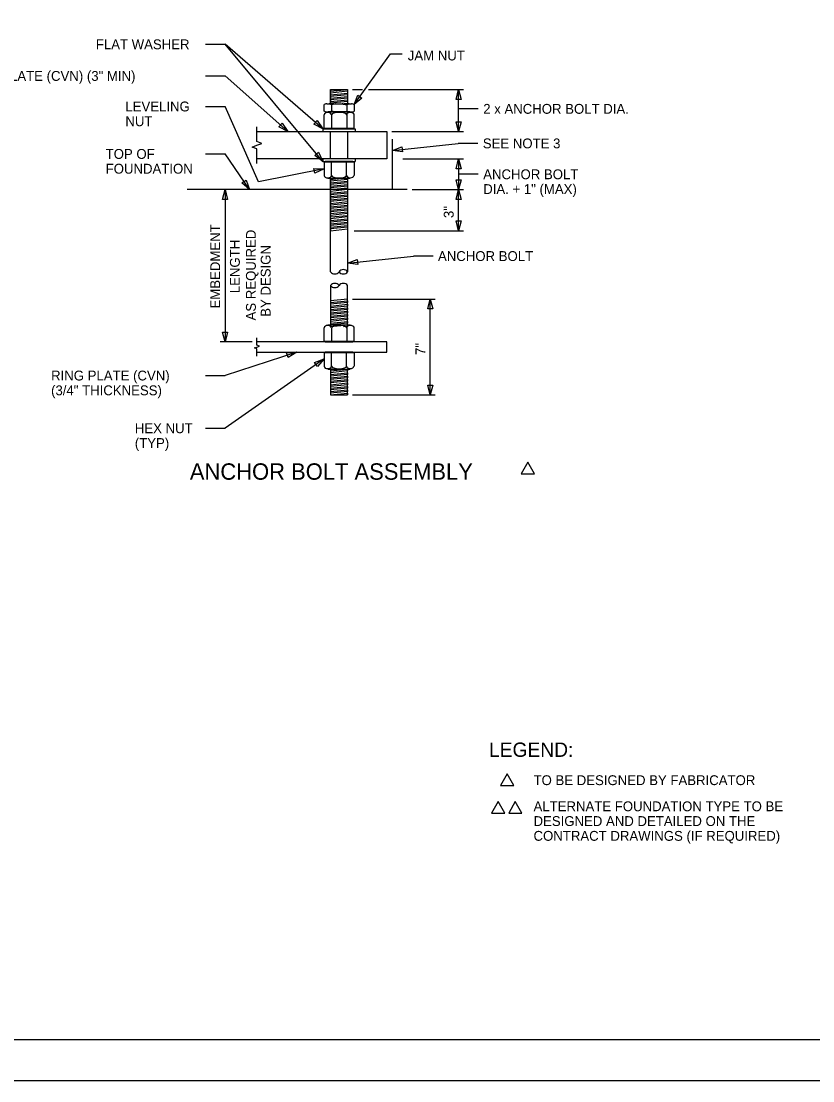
# Model space of a CAD drawing. Extents: x 1299104.6 to 1299141.4, y 239713.3 to 239735.3.
# Drawn here: x 1299118.81 to 1299128.46, y 239713.27 to 239726.18 of the extents above; entities that cross this region are included whole.
import ezdxf

# ---------------------------------------------------------------- set-up
doc = ezdxf.new("R2010")
doc.units = 0
for name, color, linetype in [('DIM TXT', 7, 'Continuous'), ('GS_plotshape_p', 7, 'Continuous'), ('Level 1', 7, 'Continuous'), ('Level 3', 7, 'Continuous'), ('Level 4', 7, 'Continuous'), ('Level 8', 7, 'Continuous')]:
    doc.layers.add(name, color=color, linetype=linetype)

msp = doc.modelspace()

# ---------------------------------------------------------------- linework, layer by layer
at = {"layer": 'DIM TXT'}
for points in [[(1299122.582, 239725.345), (1299122.582, 239725.324), (1299122.79, 239725.345), (1299122.79, 239725.324), (1299122.582, 239725.303), (1299122.582, 239725.282), (1299122.79, 239725.303), (1299122.79, 239725.282), (1299122.582, 239725.261), (1299122.582, 239725.241), (1299122.79, 239725.261), (1299122.79, 239725.241)], [(1299122.582, 239725.261), (1299122.582, 239725.241), (1299122.79, 239725.261), (1299122.79, 239725.241), (1299122.582, 239725.22), (1299122.582, 239725.199), (1299122.79, 239725.22), (1299122.79, 239725.199), (1299122.582, 239725.178), (1299122.582, 239725.178), (1299122.582, 239725.178)]]:
    msp.add_lwpolyline(points, dxfattribs=at)
for points in [[(1299124.905, 239720.667), (1299125.067, 239720.667), (1299124.986, 239720.807)], [(1299124.653, 239716.869), (1299124.815, 239716.869), (1299124.734, 239717.01)], [(1299124.543, 239716.534), (1299124.706, 239716.534), (1299124.625, 239716.675)], [(1299124.752, 239716.534), (1299124.914, 239716.534), (1299124.833, 239716.675)]]:
    msp.add_lwpolyline(points, close=True, dxfattribs=at)
at = {"layer": 'GS_plotshape_p'}
msp.add_lwpolyline([(1299104.622, 239735.273), (1299138.622, 239735.273), (1299138.622, 239713.273), (1299104.622, 239713.273)], close=True, dxfattribs=at)
at = {"layer": 'Level 1'}
msp.add_lwpolyline([(1299138.122, 239713.773), (1299106.122, 239713.773), (1299106.122, 239734.773), (1299138.122, 239734.773)], close=True, dxfattribs=at)
at = {"layer": 'Level 3'}
for p, q in [((1299122.516, 239725.166), (1299122.503, 239725.162)), ((1299122.503, 239725.08), (1299122.503, 239725.162)), ((1299122.535, 239725.17), (1299122.837, 239725.17)), ((1299122.593, 239725.159), (1299122.577, 239725.167)), ((1299122.636, 239725.169), (1299122.593, 239725.159)), ((1299122.593, 239725.159), (1299122.593, 239725.083)), ((1299122.736, 239725.169), (1299122.779, 239725.159)), ((1299122.779, 239725.159), (1299122.795, 239725.167)), ((1299122.779, 239725.159), (1299122.779, 239725.083)), ((1299122.856, 239725.166), (1299122.869, 239725.162)), ((1299122.869, 239725.162), (1299122.869, 239725.08)), ((1299122.516, 239725.075), (1299122.503, 239725.08)), ((1299122.504, 239724.876), (1299122.504, 239725.038)), ((1299122.535, 239725.072), (1299122.837, 239725.072)), ((1299122.819, 239725.072), (1299122.554, 239725.072)), ((1299122.593, 239725.083), (1299122.577, 239725.075)), ((1299122.636, 239725.073), (1299122.593, 239725.083)), ((1299122.594, 239725.036), (1299122.594, 239724.876)), ((1299122.686, 239725.072), (1299122.686, 239725.072)), ((1299122.736, 239725.073), (1299122.779, 239725.083)), ((1299122.779, 239725.083), (1299122.795, 239725.075)), ((1299122.779, 239725.037), (1299122.779, 239724.876)), ((1299122.856, 239725.075), (1299122.869, 239725.08)), ((1299122.869, 239724.876), (1299122.869, 239725.039)), ((1299122.49, 239724.866), (1299122.517, 239724.866)), ((1299122.49, 239724.866), (1299122.49, 239724.835)), ((1299122.504, 239724.876), (1299122.869, 239724.876)), ((1299122.517, 239724.875), (1299122.517, 239724.866)), ((1299122.517, 239724.866), (1299122.855, 239724.866)), ((1299122.855, 239724.875), (1299122.855, 239724.866)), ((1299122.855, 239724.866), (1299122.883, 239724.866)), ((1299122.883, 239724.866), (1299122.883, 239724.835)), ((1299121.686, 239724.834), (1299123.269, 239724.834)), ((1299123.269, 239724.834), (1299123.269, 239724.501)), ((1299123.336, 239724.126), (1299123.336, 239724.742)), ((1299123.269, 239724.501), (1299121.686, 239724.501)), ((1299122.49, 239724.501), (1299122.49, 239724.47)), ((1299122.49, 239724.47), (1299122.517, 239724.47)), ((1299122.503, 239724.46), (1299122.503, 239724.297)), ((1299122.868, 239724.46), (1299122.503, 239724.46)), ((1299122.855, 239724.47), (1299122.517, 239724.47)), ((1299122.517, 239724.461), (1299122.517, 239724.47)), ((1299122.593, 239724.299), (1299122.593, 239724.46)), ((1299122.778, 239724.3), (1299122.778, 239724.46)), ((1299122.855, 239724.461), (1299122.855, 239724.47)), ((1299122.855, 239724.47), (1299122.883, 239724.47)), ((1299122.868, 239724.46), (1299122.868, 239724.298)), ((1299122.883, 239724.501), (1299122.883, 239724.47)), ((1299122.553, 239724.264), (1299122.818, 239724.264)), ((1299123.517, 239724.126), (1299120.836, 239724.126)), ((1299122.504, 239722.281), (1299122.504, 239722.444)), ((1299122.819, 239722.477), (1299122.554, 239722.477)), ((1299122.594, 239722.441), (1299122.594, 239722.281)), ((1299122.686, 239722.477), (1299122.686, 239722.477)), ((1299122.779, 239722.442), (1299122.779, 239722.281)), ((1299122.869, 239722.281), (1299122.869, 239722.445)), ((1299123.269, 239722.272), (1299121.686, 239722.272)), ((1299122.504, 239722.281), (1299122.869, 239722.281)), ((1299122.517, 239722.281), (1299122.517, 239722.272)), ((1299122.517, 239722.272), (1299122.855, 239722.272)), ((1299122.855, 239722.281), (1299122.855, 239722.272)), ((1299123.269, 239722.147), (1299123.269, 239722.272)), ((1299121.686, 239722.147), (1299123.269, 239722.147)), ((1299122.503, 239722.137), (1299122.503, 239721.974)), ((1299122.868, 239722.137), (1299122.503, 239722.137)), ((1299122.855, 239722.147), (1299122.517, 239722.147)), ((1299122.517, 239722.138), (1299122.517, 239722.147)), ((1299122.593, 239721.976), (1299122.593, 239722.137)), ((1299122.778, 239721.977), (1299122.778, 239722.137)), ((1299122.855, 239722.138), (1299122.855, 239722.147)), ((1299122.868, 239722.137), (1299122.868, 239721.975)), ((1299122.553, 239721.941), (1299122.818, 239721.941))]:
    msp.add_line(p, q, dxfattribs=at)
for points in [[(1299122.582, 239725.17), (1299122.582, 239725.345), (1299122.79, 239725.345), (1299122.79, 239725.17)], [(1299122.709, 239725.17), (1299122.79, 239725.178), (1299122.79, 239725.178)], [(1299122.582, 239724.501), (1299122.582, 239724.834), (1299122.79, 239724.834), (1299122.79, 239724.501)], [(1299122.582, 239723.126), (1299122.582, 239724.264), (1299122.79, 239724.264), (1299122.79, 239723.126)], [(1299122.582, 239724.251), (1299122.582, 239724.251), (1299122.582, 239724.251), (1299122.713, 239724.264), (1299122.713, 239724.264)], [(1299122.582, 239722.959), (1299122.582, 239722.454)], [(1299122.79, 239722.454), (1299122.79, 239722.959)], [(1299122.582, 239721.941), (1299122.582, 239721.626), (1299122.79, 239721.626), (1299122.79, 239721.941)]]:
    msp.add_lwpolyline(points, dxfattribs=at)
for centre, radius, start, end in [((1299122.535, 239725.116), 0.0541, 90, 110.556), ((1299122.565, 239725.143), 0.0271, 63.4349, 90), ((1299122.648, 239725.116), 0.0541, 90, 102.5288), ((1299122.724, 239725.116), 0.0541, 77.4712, 90), ((1299122.807, 239725.143), 0.0271, 90, 116.5651), ((1299122.837, 239725.116), 0.0541, 69.444, 90), ((1299122.535, 239725.126), 0.0541, 249.444, 270), ((1299122.554, 239725.067), 0.00494, 90, 180), ((1299122.565, 239725.099), 0.0271, 270, 296.5651), ((1299122.648, 239725.126), 0.0541, 257.4712, 270), ((1299122.724, 239725.126), 0.0541, 270, 282.5288), ((1299122.807, 239725.099), 0.0271, 243.4349, 270), ((1299122.819, 239725.067), 0.00494, 0, 90), ((1299122.837, 239725.126), 0.0541, 270, 290.556), ((1299122.553, 239724.269), 0.00494, 180, 270), ((1299122.798, 239724.298), 0.0213, 180, 270), ((1299122.818, 239724.269), 0.00494, 270, 0), ((1299122.634, 239723.165), 0.0651, 216.8699, 323.1301), ((1299122.738, 239723.087), 0.0651, 36.8699, 143.1301), ((1299122.738, 239723.165), 0.0651, 216.8699, 323.1301), ((1299122.634, 239722.92), 0.0651, 36.8699, 143.1301), ((1299122.634, 239722.998), 0.0651, 216.8699, 323.1301), ((1299122.738, 239722.92), 0.0651, 36.8699, 143.1301), ((1299122.554, 239722.472), 0.00494, 90, 180), ((1299122.819, 239722.472), 0.00494, 0, 90), ((1299122.553, 239721.946), 0.00494, 180, 270), ((1299122.818, 239721.946), 0.00494, 270, 0)]:
    msp.add_arc(centre, radius, start, end, dxfattribs=at)
for centre, major_axis, ratio, start_param, end_param in [((1299122.549, 239725.035), (0.0451, 0.0005), 0.679853, 0, 3.035161), ((1299122.686, 239725.036), (-0.0927, -0.0005), 0.335964, 3.141593, 6.283185), ((1299122.824, 239725.036), (-0.0451, 0.0005), 0.679853, 3.248025, 6.283185), ((1299122.548, 239724.3), (0.0451, -0.0005), 0.679853, 3.248025, 6.283185), ((1299122.686, 239724.3), (0.0927, 0.0005), 0.335964, 3.141593, 6.283185), ((1299122.823, 239724.301), (-0.0451, -0.0005), 0.679853, 0, 3.035161), ((1299122.549, 239722.441), (0.0451, 0.0005), 0.679853, 0, 3.035161), ((1299122.686, 239722.442), (-0.0927, -0.0005), 0.335964, 3.141593, 6.283185), ((1299122.824, 239722.442), (-0.0451, 0.0005), 0.679853, 3.248025, 6.283185), ((1299122.548, 239721.977), (0.0451, -0.0005), 0.679853, 3.248025, 6.283185), ((1299122.686, 239721.977), (0.0927, 0.0005), 0.335964, 3.141593, 6.283185), ((1299122.823, 239721.978), (-0.0451, -0.0005), 0.679853, 0, 3.035161)]:
    msp.add_ellipse(centre, major_axis=major_axis, ratio=ratio, start_param=start_param, end_param=end_param, dxfattribs=at)
at = {"layer": 'Level 4'}
for points in [[(1299122.79, 239724.251), (1299122.582, 239724.23), (1299122.582, 239724.209), (1299122.79, 239724.23), (1299122.79, 239724.209), (1299122.582, 239724.188), (1299122.582, 239724.168), (1299122.79, 239724.188), (1299122.79, 239724.168), (1299122.582, 239724.147), (1299122.582, 239724.126), (1299122.79, 239724.147), (1299122.79, 239724.126), (1299122.582, 239724.105), (1299122.582, 239724.084), (1299122.79, 239724.105), (1299122.79, 239724.084), (1299122.582, 239724.063), (1299122.582, 239724.043), (1299122.79, 239724.063), (1299122.79, 239724.043)], [(1299122.79, 239724.043), (1299122.582, 239724.022), (1299122.582, 239724.001), (1299122.79, 239724.022), (1299122.79, 239724.001), (1299122.582, 239723.98), (1299122.582, 239723.959), (1299122.79, 239723.98), (1299122.79, 239723.959), (1299122.582, 239723.938), (1299122.582, 239723.918), (1299122.79, 239723.938), (1299122.79, 239723.918), (1299122.582, 239723.897), (1299122.582, 239723.876), (1299122.79, 239723.897), (1299122.79, 239723.876), (1299122.582, 239723.855), (1299122.582, 239723.834), (1299122.79, 239723.855), (1299122.79, 239723.834)], [(1299122.79, 239723.834), (1299122.582, 239723.813), (1299122.582, 239723.793), (1299122.79, 239723.813), (1299122.79, 239723.793), (1299122.582, 239723.772), (1299122.582, 239723.751), (1299122.79, 239723.772), (1299122.79, 239723.751), (1299122.582, 239723.73), (1299122.582, 239723.709), (1299122.79, 239723.73), (1299122.79, 239723.709), (1299122.582, 239723.688), (1299122.582, 239723.668), (1299122.79, 239723.688), (1299122.79, 239723.668), (1299122.582, 239723.647), (1299122.582, 239723.626), (1299122.79, 239723.647), (1299122.79, 239723.626)], [(1299122.79, 239722.793), (1299122.582, 239722.772), (1299122.582, 239722.751), (1299122.79, 239722.772), (1299122.79, 239722.751)], [(1299122.79, 239722.751), (1299122.582, 239722.73), (1299122.582, 239722.709), (1299122.79, 239722.73), (1299122.79, 239722.709), (1299122.582, 239722.688), (1299122.582, 239722.668), (1299122.79, 239722.688), (1299122.79, 239722.668), (1299122.582, 239722.647), (1299122.582, 239722.626), (1299122.79, 239722.647), (1299122.79, 239722.626), (1299122.582, 239722.605), (1299122.582, 239722.584), (1299122.79, 239722.605), (1299122.79, 239722.584), (1299122.582, 239722.563), (1299122.582, 239722.543), (1299122.79, 239722.563), (1299122.79, 239722.543)], [(1299122.79, 239722.543), (1299122.582, 239722.522), (1299122.582, 239722.501), (1299122.79, 239722.522), (1299122.79, 239722.501), (1299122.582, 239722.48), (1299122.582, 239722.459), (1299122.79, 239722.48), (1299122.79, 239722.459), (1299122.738, 239722.454)], [(1299122.609, 239721.941), (1299122.609, 239721.941), (1299122.582, 239721.938), (1299122.582, 239721.918), (1299122.79, 239721.938), (1299122.79, 239721.918), (1299122.582, 239721.897), (1299122.582, 239721.876), (1299122.79, 239721.897), (1299122.79, 239721.876), (1299122.582, 239721.855), (1299122.582, 239721.834), (1299122.79, 239721.855), (1299122.79, 239721.834)], [(1299122.79, 239721.834), (1299122.582, 239721.813), (1299122.582, 239721.793), (1299122.79, 239721.813), (1299122.79, 239721.793), (1299122.582, 239721.772), (1299122.582, 239721.751), (1299122.79, 239721.772), (1299122.79, 239721.751), (1299122.582, 239721.73), (1299122.582, 239721.709), (1299122.79, 239721.73), (1299122.79, 239721.709), (1299122.582, 239721.688), (1299122.582, 239721.668), (1299122.79, 239721.688), (1299122.79, 239721.668), (1299122.582, 239721.647), (1299122.582, 239721.626), (1299122.79, 239721.647), (1299122.79, 239721.626)]]:
    msp.add_lwpolyline(points, dxfattribs=at)
at = {"layer": 'Level 8'}
for p, q in [((1299121.057, 239725.896), (1299121.297, 239725.896)), ((1299122.49, 239724.866), (1299121.297, 239725.896)), ((1299122.49, 239724.47), (1299121.297, 239725.896)), ((1299122.869, 239725.162), (1299123.312, 239725.779)), ((1299123.312, 239725.779), (1299123.455, 239725.779)), ((1299121.057, 239725.511), (1299121.297, 239725.511)), ((1299122.063, 239724.834), (1299121.297, 239725.511)), ((1299122.85, 239725.345), (1299122.97, 239725.345)), ((1299123.046, 239725.345), (1299124.202, 239725.345)), ((1299124.142, 239724.834), (1299124.142, 239725.345)), ((1299121.057, 239725.139), (1299121.297, 239725.139)), ((1299121.703, 239724.221), (1299121.297, 239725.139)), ((1299124.382, 239725.11), (1299124.142, 239725.11)), ((1299121.686, 239724.712), (1299121.686, 239724.89)), ((1299123.329, 239724.834), (1299124.202, 239724.834)), ((1299121.626, 239724.645), (1299121.686, 239724.668)), ((1299121.686, 239724.623), (1299121.626, 239724.645)), ((1299121.746, 239724.69), (1299121.686, 239724.712)), ((1299121.686, 239724.668), (1299121.746, 239724.69)), ((1299121.686, 239724.445), (1299121.686, 239724.623)), ((1299123.336, 239724.604), (1299124.137, 239724.689)), ((1299124.377, 239724.689), (1299124.137, 239724.689)), ((1299121.057, 239724.561), (1299121.297, 239724.561)), ((1299121.596, 239724.126), (1299121.297, 239724.561)), ((1299123.463, 239724.501), (1299124.202, 239724.501)), ((1299124.142, 239724.501), (1299124.142, 239724.126)), ((1299122.504, 239724.379), (1299121.703, 239724.221)), ((1299124.382, 239724.313), (1299124.142, 239724.313)), ((1299121.297, 239724.126), (1299121.297, 239722.272)), ((1299123.577, 239724.126), (1299124.202, 239724.126)), ((1299123.577, 239724.126), (1299124.202, 239724.126)), ((1299124.142, 239723.626), (1299124.142, 239724.126)), ((1299122.869, 239723.626), (1299124.202, 239723.626)), ((1299122.79, 239723.232), (1299123.591, 239723.317)), ((1299123.831, 239723.317), (1299123.591, 239723.317)), ((1299122.85, 239722.793), (1299123.857, 239722.793)), ((1299123.797, 239721.626), (1299123.797, 239722.793)), ((1299121.626, 239722.272), (1299121.237, 239722.272)), ((1299121.686, 239722.232), (1299121.686, 239722.32)), ((1299122.17, 239722.147), (1299121.297, 239721.862)), ((1299121.656, 239722.198), (1299121.686, 239722.209)), ((1299121.686, 239722.187), (1299121.656, 239722.198)), ((1299121.716, 239722.22), (1299121.686, 239722.232)), ((1299121.686, 239722.209), (1299121.716, 239722.22)), ((1299121.686, 239722.098), (1299121.686, 239722.187)), ((1299122.504, 239722.066), (1299121.297, 239721.22)), ((1299121.057, 239721.862), (1299121.297, 239721.862)), ((1299122.85, 239721.626), (1299123.857, 239721.626)), ((1299121.057, 239721.22), (1299121.297, 239721.22))]:
    msp.add_line(p, q, dxfattribs=at)
for points in [[(1299122.963, 239725.242), (1299122.869, 239725.162), (1299122.914, 239725.277)], [(1299124.112, 239725.225), (1299124.142, 239725.345), (1299124.172, 239725.225)], [(1299121.993, 239724.936), (1299122.063, 239724.834), (1299121.953, 239724.891)], [(1299122.42, 239724.969), (1299122.49, 239724.866), (1299122.38, 239724.924)], [(1299124.172, 239724.954), (1299124.142, 239724.834), (1299124.112, 239724.954)], [(1299123.458, 239724.587), (1299123.336, 239724.604), (1299123.452, 239724.647)], [(1299122.437, 239724.581), (1299122.49, 239724.47), (1299122.39, 239724.543)], [(1299124.112, 239724.381), (1299124.142, 239724.501), (1299124.172, 239724.381)], [(1299122.38, 239724.385), (1299122.504, 239724.379), (1299122.392, 239724.326)], [(1299121.553, 239724.242), (1299121.596, 239724.126), (1299121.503, 239724.208)], [(1299124.172, 239724.246), (1299124.142, 239724.126), (1299124.112, 239724.246)], [(1299121.267, 239724.006), (1299121.297, 239724.126), (1299121.327, 239724.006)], [(1299124.112, 239724.006), (1299124.142, 239724.126), (1299124.172, 239724.006)], [(1299124.172, 239723.746), (1299124.142, 239723.626), (1299124.112, 239723.746)], [(1299122.913, 239723.215), (1299122.79, 239723.232), (1299122.906, 239723.275)], [(1299123.767, 239722.673), (1299123.797, 239722.793), (1299123.827, 239722.673)], [(1299121.327, 239722.392), (1299121.297, 239722.272), (1299121.267, 239722.392)], [(1299122.047, 239722.138), (1299122.17, 239722.147), (1299122.065, 239722.081)], [(1299122.388, 239722.022), (1299122.504, 239722.066), (1299122.423, 239721.973)], [(1299123.827, 239721.746), (1299123.797, 239721.626), (1299123.767, 239721.746)]]:
    msp.add_lwpolyline(points, close=True, dxfattribs=at)

# ---------------------------------------------------------------- texts
at = {"layer": 'DIM TXT'}
for s, height, p in [('FLAT WASHER', 0.12, (1299119.723, 239725.836)), ('JAM NUT', 0.12, (1299123.523, 239725.7)), ('BASE PLATE (CVN) (3" MIN)', 0.12, (1299118.098, 239725.451)), ('LEVELING', 0.12, (1299120.083, 239725.079)), ('2 x ANCHOR BOLT DIA.', 0.12, (1299124.442, 239725.05)), ('NUT', 0.12, (1299120.083, 239724.899)), ('SEE NOTE 3', 0.12, (1299124.437, 239724.629)), ('TOP OF', 0.12, (1299119.843, 239724.501)), ('FOUNDATION', 0.12, (1299119.843, 239724.321)), ('ANCHOR BOLT', 0.12, (1299124.442, 239724.253)), ('DIA. + 1" (MAX)', 0.12, (1299124.442, 239724.073)), ('ANCHOR BOLT', 0.12, (1299123.891, 239723.257)), ('RING PLATE (CVN)', 0.12, (1299119.178, 239721.802)), ('(3/4" THICKNESS)', 0.12, (1299119.178, 239721.622)), ('HEX NUT', 0.12, (1299120.198, 239721.16)), ('(TYP)', 0.12, (1299120.198, 239720.98)), ('ANCHOR BOLT ASSEMBLY', 0.2, (1299120.868, 239720.593)), ('LEGEND:', 0.175, (1299124.513, 239717.218)), ('TO BE DESIGNED BY FABRICATOR', 0.12, (1299125.055, 239716.874)), ('ALTERNATE FOUNDATION TYPE TO BE', 0.12, (1299125.055, 239716.556)), ('DESIGNED AND DETAILED ON THE ', 0.12, (1299125.055, 239716.376)), ('CONTRACT DRAWINGS (IF REQUIRED)', 0.12, (1299125.055, 239716.196))]:
    msp.add_text(s, height=height, dxfattribs=at).set_placement(p)
for s, p in [('3"', (1299124.082, 239723.78)), ('EMBEDMENT', (1299121.237, 239722.679)), ('AS REQUIRED', (1299121.672, 239722.533)), ('LENGTH', (1299121.477, 239722.865)), (' BY DESIGN', (1299121.852, 239722.533)), ('7"', (1299123.737, 239722.113))]:
    msp.add_text(s, height=0.12, rotation=90, dxfattribs=at).set_placement(p)

doc.saveas('drawing.dxf')
